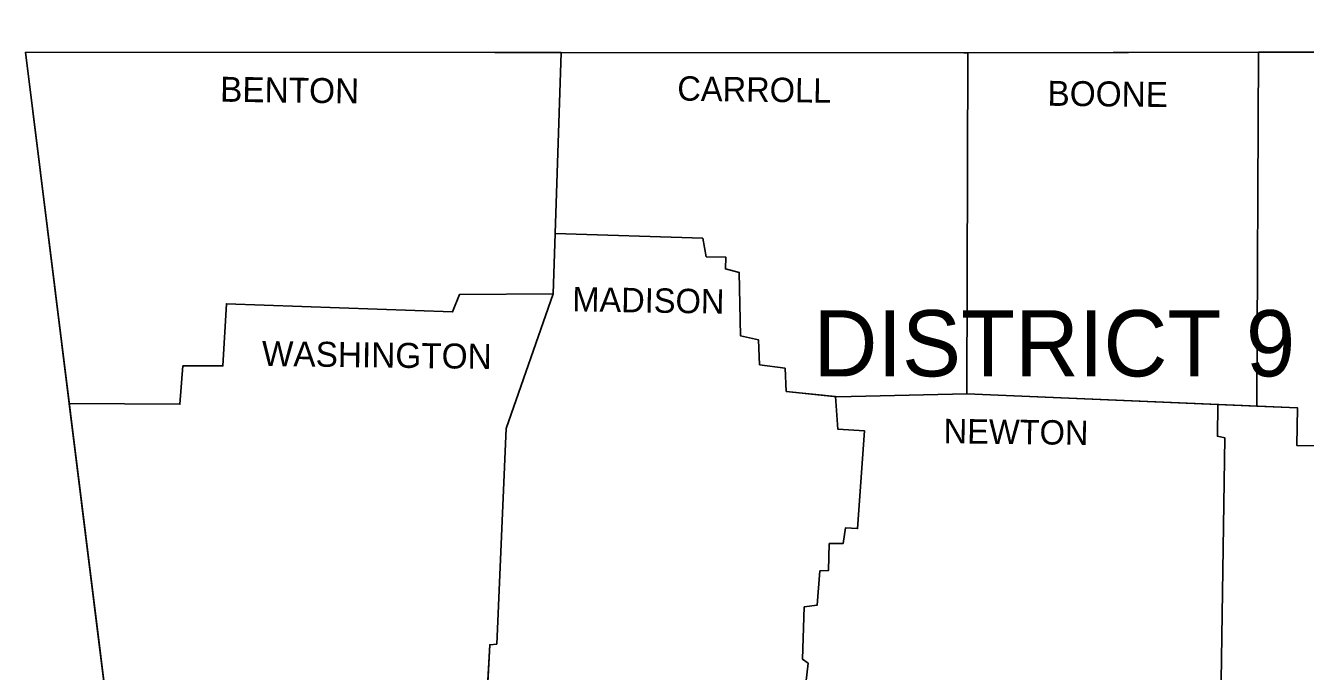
# Model space of a CAD drawing. Extents: x -28335 to 1228743, y -22428 to 152440.
# Drawn here: x 24268 to 29265, y 15008 to 17527 of the extents above; entities that cross this region are included whole.
import ezdxf

# ---------------------------------------------------------------- set-up
doc = ezdxf.new("R2010")
doc.units = 0
doc.layers.add('R_Draft', color=7, linetype='Continuous')
doc.layers.add('R_No Plot', color=7, linetype='Continuous')

msp = doc.modelspace()

# ---------------------------------------------------------------- linework, layer by layer
at = {"layer": 'R_Draft'}
for points in [[(24268.3, 17422.7), (27931.3, 17420.4), (31145.8, 17427.2), (34937.9, 17486.1), (36695.7, 17526.9)], [(24268.3, 17422.7), (24737.2, 13657.8), (24533.3, 7512.2)], [(26359.6, 17421.4), (26327.5, 16480.3)], [(26335.5, 16716.6), (26911.9, 16697.8), (26925.5, 16625.3), (27002.5, 16623.1), (27000.3, 16577.8), (27054.6, 16564.2), (27059.2, 16317.2), (27129.4, 16301.4), (27133.9, 16204), (27233.6, 16190.4), (27238.1, 16099.8), (27435.2, 16079.4), (27942.6, 16090.7), (27947.2, 17420.5)], [(29082.2, 17422.9), (29075.2, 16043)], [(24439, 16052.3), (24870.9, 16049.9), (24882.2, 16199.5), (25038.5, 16199.5), (25052.1, 16441.8), (25935.6, 16410.1), (25962.7, 16478.1), (26327.5, 16480.3), (26144, 15954.8), (26107.7, 15114.4), (26080.5, 15112.1), (26066.9, 14858.4), (26200.6, 14847.1), (26221, 14867.5), (27301.5, 14847.1), (27312.9, 14727)], [(27942.6, 16090.7), (29233.8, 16036.4), (29231.6, 15889.1), (30421.8, 15880)], [(27430.3, 16079.9), (27439.7, 15952.5), (27543.9, 15945.7), (27516.7, 15565.2), (27469.2, 15567.5), (27460.1, 15506.3), (27405.7, 15506.3), (27403.5, 15402.1), (27369.5, 15399.8), (27358.2, 15266.2), (27308.3, 15259.4), (27301.5, 15055.5), (27324.2, 15039.6), (27301.5, 14847.1)], [(28923.6, 16049.4), (28921.2, 15925.4), (28950.7, 15918.6), (28932.4, 14713.9)]]:
    msp.add_lwpolyline(points, dxfattribs=at)
at = {"layer": 'R_No Plot'}
for p, q in [((26359.6, 17421.4), (24268.3, 17422.7)), ((24268.3, 17422.7), (24439, 16052.3)), ((26359.6, 17421.4), (26335.5, 16716.6)), ((27931.3, 17420.4), (26359.6, 17421.4)), ((27947.2, 17420.5), (27931.3, 17420.4)), ((27947.2, 17420.5), (27942.6, 16090.7)), ((29082.2, 17422.9), (27947.2, 17420.5)), ((29075.2, 16043), (29082.2, 17422.9)), ((29082.2, 17422.9), (29075.2, 16043)), ((30078.9, 17425), (29082.2, 17422.9)), ((26335.5, 16716.6), (26327.5, 16480.3)), ((26911.9, 16697.8), (26335.5, 16716.6)), ((26925.5, 16625.3), (26911.9, 16697.8)), ((27054.6, 16564.2), (27000.3, 16577.8)), ((27059.2, 16317.2), (27054.6, 16564.2)), ((25052.1, 16441.8), (25038.5, 16199.5)), ((25935.6, 16410.1), (25052.1, 16441.8)), ((25962.7, 16478.1), (25935.6, 16410.1)), ((26327.5, 16480.3), (25962.7, 16478.1)), ((27129.4, 16301.4), (27059.2, 16317.2)), ((25038.5, 16199.5), (24882.2, 16199.5)), ((27430.3, 16079.9), (27238.1, 16099.8)), ((27942.6, 16090.7), (27435.2, 16079.4)), ((27942.6, 16090.7), (29075.2, 16043)), ((28923.6, 16049.4), (27942.6, 16090.7)), ((24439, 16052.3), (24587.9, 14856.6)), ((27435.2, 16079.4), (27430.3, 16079.9)), ((27308.3, 15259.4), (27358.2, 15266.2)), ((26067.3, 14865.5), (26080.5, 15112.1)), ((26080.5, 15112.1), (26107.7, 15114.4))]:
    msp.add_line(p, q, dxfattribs=at)
for points in [[(26327.5, 16480.3), (26335.5, 16716.6), (26359.6, 17421.4)], [(26335.5, 16716.6), (26911.9, 16697.8), (26925.5, 16625.3), (27002.5, 16623.1), (27000.3, 16577.8), (27054.6, 16564.2), (27059.2, 16317.2), (27129.4, 16301.4), (27133.9, 16204), (27233.6, 16190.4), (27238.1, 16099.8), (27435.2, 16079.4), (27942.6, 16090.7), (27947.2, 17420.5)], [(27000.3, 16577.8), (27002.5, 16623.1), (26925.5, 16625.3)], [(24439, 16052.3), (24870.9, 16049.9), (24882.2, 16199.5), (25038.5, 16199.5), (25052.1, 16441.8), (25935.6, 16410.1), (25962.7, 16478.1), (26327.5, 16480.3)], [(26327.5, 16480.3), (26144, 15954.8), (26107.7, 15114.4), (26080.5, 15112.1), (26067.3, 14865.5), (26066.9, 14858.4), (26200.6, 14847.1), (26221, 14867.5), (26825.8, 14856.1)], [(26107.7, 15114.4), (26144, 15954.8), (26327.5, 16480.3)], [(27238.1, 16099.8), (27233.6, 16190.4), (27133.9, 16204), (27129.4, 16301.4)], [(24882.2, 16199.5), (24870.9, 16049.9), (24439, 16052.3)], [(27430.3, 16079.9), (27439.7, 15952.5), (27543.9, 15945.7), (27516.7, 15565.2), (27469.2, 15567.5), (27460.1, 15506.3), (27405.7, 15506.3), (27403.5, 15402.1), (27369.5, 15399.8), (27358.2, 15266.2), (27308.3, 15259.4), (27301.5, 15055.5), (27324.2, 15039.6), (27301.5, 14847.1)], [(27516.7, 15565.2), (27543.9, 15945.7), (27439.7, 15952.5), (27430.3, 16079.9)], [(28932.4, 14713.9), (28950.7, 15918.6), (28921.2, 15925.4), (28923.6, 16049.4)], [(28923.6, 16049.4), (28921.2, 15925.4), (28950.7, 15918.6), (28932.4, 14713.9)], [(30421.8, 15880), (29231.6, 15889.1), (29233.8, 16036.4), (29075.2, 16043), (28923.6, 16049.4)], [(29075.2, 16043), (29233.8, 16036.4), (29231.6, 15889.1), (30421.8, 15880)], [(27460.1, 15506.3), (27469.2, 15567.5), (27516.7, 15565.2)], [(27358.2, 15266.2), (27369.5, 15399.8), (27403.5, 15402.1), (27405.7, 15506.3), (27460.1, 15506.3)], [(27301.5, 14847.1), (27324.2, 15039.6), (27301.5, 15055.5), (27308.3, 15259.4)]]:
    msp.add_lwpolyline(points, dxfattribs=at)

# ---------------------------------------------------------------- texts
at = {"layer": 'R_Draft'}
for s, height, rotation, p in [('BENTON', 97.42, 359.2527, (25027.2, 17230.1)), ('CARROLL', 95.15, 359.1481, (26812.2, 17234.7)), ('BOONE', 97.42, 359.4001, (28257.5, 17214.3)), ('MADISON', 95.15, 359.0906, (26402.2, 16412.4)), ('WASHINGTON', 97.4, 359.232, (25190.3, 16199.5)), ('NEWTON', 95.15, 359.2717, (27852, 15898.2))]:
    msp.add_text(s, height=height, rotation=rotation, dxfattribs=at).set_placement(p)
msp.add_text('DISTRICT 9', height=258.24, dxfattribs=at).set_placement((27344.6, 16158.7))

doc.saveas('drawing.dxf')
